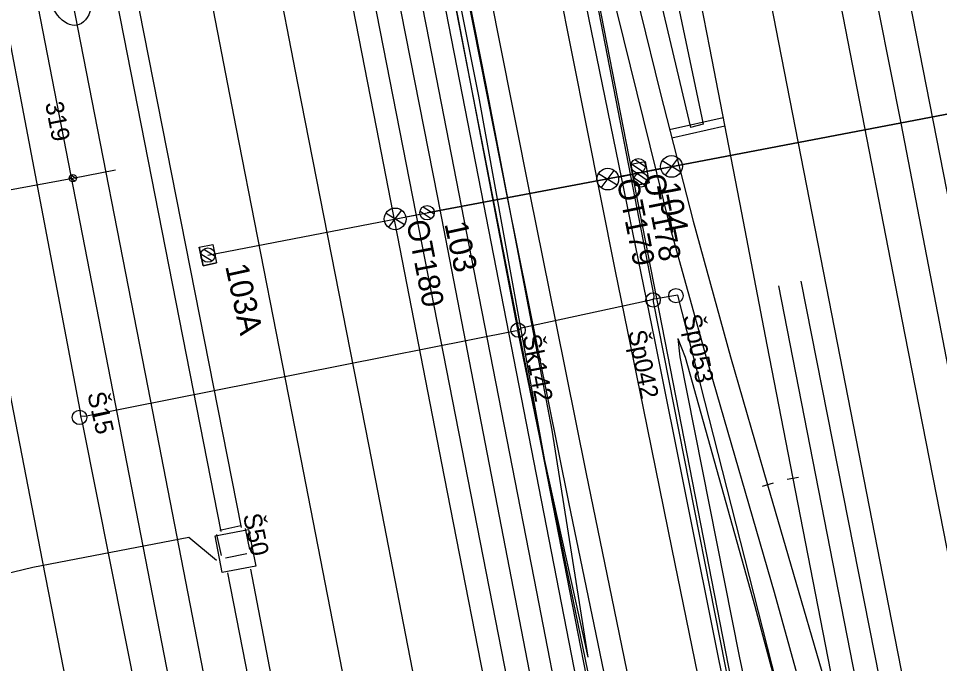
# Model space of a CAD drawing. Extents: x -545846 to -545044, y -1122650 to -1119108.
# Drawn here: x -545534.5 to -545470.6, y -1120354 to -1120309.2 of the extents above; entities that cross this region are included whole.
import ezdxf

# ---------------------------------------------------------------- set-up
doc = ezdxf.new("R2010")
doc.units = 0
for name, color, linetype in [('osvětlené plochy-hodnota-obrys', 7, 'Continuous'), ('Vrstva 1', 7, 'Continuous'), ('Vrstva 1 - Koleje', 7, 'Continuous'), ('Vrstva 11', 7, 'Continuous'), ('Vrstva 11 - Trakce', 7, 'Continuous'), ('Vrstva 12 - Trakce zaklady', 7, 'Continuous'), ('Vrstva 2 - Vyhybky', 7, 'Continuous'), ('Vrstva 25', 7, 'Continuous'), ('Vrstva 26', 7, 'Continuous'), ('Vrstva 28 - zabzar', 7, 'Continuous'), ('Vrstva 34', 7, 'Continuous'), ('Vrstva 35', 7, 'Continuous'), ('Vrstva 36', 7, 'Continuous'), ('Vrstva 4 - Teren - stezky - prechody - plochy', 7, 'Continuous'), ('Vrstva 43', 7, 'Continuous'), ('Vrstva 44', 7, 'Continuous'), ('Vrstva 49', 7, 'Continuous'), ('Vrstva 7 - Namezniky-vystroj', 7, 'Continuous')]:
    doc.layers.add(name, color=color, linetype=linetype)

msp = doc.modelspace()

# ---------------------------------------------------------------- linework, layer by layer
at = {"layer": 'osvětlené plochy-hodnota-obrys'}
for points in [[(-545607.519, -1119727.517), (-545482.536, -1120367.871), (-545465.73, -1120446.743)], [(-545611.105, -1119760.367), (-545492.389, -1120368.615), (-545475.582, -1120447.487)], [(-545605.8, -1119934.355), (-545489.142, -1120534.587)]]:
    msp.add_lwpolyline(points, dxfattribs=at)
at = {"layer": 'Vrstva 1'}
for points in [[(-545474.761, -1120297.023), (-545472.421, -1120309.053), (-545468.418, -1120329.586), (-545465.176, -1120346.189), (-545461.046, -1120367.441), (-545459.79, -1120373.88)], [(-545479.428, -1120297.932), (-545477.11, -1120309.858), (-545472.957, -1120331.165), (-545469.82, -1120347.196), (-545465.692, -1120368.38), (-545464.44, -1120374.79)], [(-545484.065, -1120298.835), (-545481.72, -1120310.868), (-545477.659, -1120331.714), (-545474.512, -1120347.852), (-545470.27, -1120369.601), (-545469.079, -1120375.698)], [(-545512.079, -1120304.29), (-545509.652, -1120316.729), (-545504.92, -1120341.014), (-545501.351, -1120359.337), (-545498.197, -1120375.55), (-545497.107, -1120381.183)], [(-545516.751, -1120305.199), (-545515.098, -1120313.673), (-545510.162, -1120338.881), (-545507.312, -1120353.561), (-545502.757, -1120376.885), (-545501.739, -1120382.09)], [(-545530.725, -1120307.92), (-545525.484, -1120334.817), (-545521.174, -1120356.99), (-545516.72, -1120379.861), (-545515.757, -1120384.834)], [(-545521.096, -1120307.884), (-545519.375, -1120316.749), (-545514.88, -1120339.783), (-545511.839, -1120355.373), (-545507.449, -1120377.832), (-545506.438, -1120383.01)], [(-545540.046, -1120309.735), (-545537.636, -1120322.066), (-545534.947, -1120335.844), (-545532.811, -1120346.828), (-545526.072, -1120381.352), (-545525.038, -1120386.65)]]:
    msp.add_lwpolyline(points, dxfattribs=at)
msp.add_ellipse((-545531.017, -1120306.509), major_axis=(0.614, -3.151), ratio=0.521067, dxfattribs=at)
at = {"layer": 'Vrstva 1 - Koleje'}
for points in [[(-545518.735, -1120170.873), (-545517.092, -1120179.279), (-545515.239, -1120188.8), (-545513.529, -1120197.566), (-545510.734, -1120211.886), (-545508.807, -1120221.766), (-545506.999, -1120231.05), (-545505.057, -1120241.005), (-545503.311, -1120249.961), (-545501.333, -1120260.123), (-545500.069, -1120266.614), (-545498.099, -1120276.734), (-545496.21, -1120286.398), (-545494.099, -1120296.551), (-545493.353, -1120299.814), (-545491.303, -1120308.782), (-545489.949, -1120314.331), (-545487.646, -1120323.268), (-545485.059, -1120332.675), (-545482.488, -1120341.567), (-545476.909, -1120360.737), (-545474.458, -1120373.309), (-545474.305, -1120374.094)], [(-545532.743, -1120173.486), (-545531.198, -1120181.414), (-545529.444, -1120190.408), (-545527.614, -1120199.79), (-545525.849, -1120208.859), (-545524.083, -1120217.878), (-545522.353, -1120226.804), (-545520.544, -1120236.067), (-545518.751, -1120245.244), (-545517.019, -1120254.134), (-545515.322, -1120262.818), (-545513.441, -1120272.491), (-545511.549, -1120282.172), (-545509.7, -1120291.668), (-545508.107, -1120299.843), (-545506.179, -1120309.724), (-545504.441, -1120318.636), (-545502.519, -1120328.489), (-545500.578, -1120338.445), (-545498.519, -1120349.006), (-545496.544, -1120359.143), (-545494.419, -1120370.064), (-545492.599, -1120379.398), (-545492.429, -1120380.268)], [(-545527.503, -1120175.582), (-545525.637, -1120185.143), (-545523.723, -1120194.953), (-545521.869, -1120204.454), (-545519.868, -1120214.706), (-545518.049, -1120224.023), (-545516.204, -1120233.485), (-545514.302, -1120243.235), (-545512.475, -1120252.605), (-545510.119, -1120264.679), (-545508.199, -1120274.552), (-545506.603, -1120282.757), (-545504.862, -1120291.702), (-545502.966, -1120301.337), (-545501.126, -1120310.611), (-545498.972, -1120321.418), (-545497.182, -1120330.346), (-545495.087, -1120340.689), (-545493.131, -1120350.244), (-545491.235, -1120359.489), (-545489.284, -1120368.922), (-545487.138, -1120379.232)], [(-545522.376, -1120177.035), (-545520.607, -1120186.115), (-545518.736, -1120195.699), (-545516.972, -1120204.753), (-545515.112, -1120214.314), (-545513.215, -1120224.036), (-545511.543, -1120232.598), (-545509.745, -1120241.825), (-545507.98, -1120250.879), (-545506.022, -1120260.921), (-545504.236, -1120270.098), (-545502.408, -1120279.461), (-545500.568, -1120288.895), (-545498.693, -1120298.415), (-545497.048, -1120306.715), (-545495.06, -1120316.74), (-545493.074, -1120326.625), (-545491.128, -1120336.251), (-545489.136, -1120346.042), (-545486.961, -1120356.657), (-545485.254, -1120364.907), (-545483.638, -1120372.702), (-545482.464, -1120378.318)], [(-545491.058, -1120287.923), (-545489.405, -1120296.386), (-545488.935, -1120298.789), (-545487.964, -1120303.745), (-545486.509, -1120311.24), (-545484.296, -1120322.688), (-545482.535, -1120331.849), (-545480.73, -1120341.135), (-545476.909, -1120360.737), (-545474.458, -1120373.309), (-545474.305, -1120374.094)]]:
    msp.add_lwpolyline(points, dxfattribs=at)
at = {"layer": 'Vrstva 11'}
for p, q in [((-545530.553, -1120320.486), (-545530.931, -1120320.23)), ((-545530.445, -1120320.332), (-545530.829, -1120320.073))]:
    msp.add_line(p, q, dxfattribs=at)
msp.add_lwpolyline([(-545554.83, -1120324.712), (-545530.687, -1120320.277), (-545527.734, -1120319.705)], dxfattribs=at)
msp.add_circle((-545530.687, -1120320.277), 0.25, dxfattribs=at)
at = {"layer": 'Vrstva 11 - Trakce'}
for p, q in [((-545491.701, -1120318.979), (-545490.962, -1120319.48)), ((-545491.933, -1120319.274), (-545491.15, -1120319.807)), ((-545491.747, -1120320.26), (-545490.965, -1120320.791)), ((-545491.516, -1120319.964), (-545490.775, -1120320.467)), ((-545506.388, -1120322.268), (-545505.619, -1120322.761)), ((-545506.596, -1120322.579), (-545505.817, -1120323.08)), ((-545521.799, -1120325.523), (-545521.02, -1120326.024)), ((-545521.591, -1120325.212), (-545520.822, -1120325.705))]:
    msp.add_line(p, q, dxfattribs=at)
msp.add_lwpolyline([(-545521.313, -1120325.623), (-545506.11, -1120322.679), (-545491.363, -1120319.905), (-545468.705, -1120315.571), (-545444.245, -1120310.64)], dxfattribs=at)
for centre in [(-545491.457, -1120319.414), (-545491.269, -1120320.396), (-545506.11, -1120322.679), (-545521.313, -1120325.623)]:
    msp.add_circle(centre, 0.5, dxfattribs=at)
at = {"layer": 'Vrstva 12 - Trakce zaklady'}
for p, q in [((-545491.972, -1120319.298), (-545490.99, -1120319.111)), ((-545491.689, -1120320.781), (-545490.707, -1120320.594)), ((-545521.928, -1120325.082), (-545520.968, -1120324.874)), ((-545521.648, -1120326.366), (-545520.724, -1120326.164))]:
    msp.add_line(p, q, dxfattribs=at)
for points in [[(-545491.689, -1120320.781), (-545491.972, -1120319.298), (-545490.99, -1120319.111), (-545490.707, -1120320.594), (-545491.689, -1120320.781)], [(-545490.99, -1120319.111), (-545490.99, -1120319.111), (-545490.707, -1120320.594), (-545490.707, -1120320.594)], [(-545491.972, -1120319.298), (-545491.972, -1120319.298), (-545491.689, -1120320.781), (-545491.689, -1120320.781)], [(-545521.928, -1120325.082), (-545520.968, -1120324.874), (-545520.724, -1120326.164), (-545521.648, -1120326.366), (-545521.928, -1120325.082)], [(-545520.968, -1120324.874), (-545520.968, -1120324.874), (-545520.724, -1120326.164), (-545520.724, -1120326.164)], [(-545521.928, -1120325.082), (-545521.928, -1120325.082), (-545521.648, -1120326.366), (-545521.648, -1120326.366)]]:
    msp.add_lwpolyline(points, dxfattribs=at)
at = {"layer": 'Vrstva 2 - Vyhybky'}
for p, q in [((-545482.104, -1120341.456), (-545482.872, -1120341.678)), ((-545480.337, -1120341.059), (-545481.123, -1120341.211))]:
    msp.add_line(p, q, dxfattribs=at)
for points in [[(-545480.73, -1120341.135), (-545476.909, -1120360.737), (-545474.458, -1120373.309), (-545474.305, -1120374.094)], [(-545482.488, -1120341.567), (-545476.909, -1120360.737)]]:
    msp.add_lwpolyline(points, dxfattribs=at)
at = {"layer": 'Vrstva 25'}
for p, q in [((-545488.513, -1120319.862), (-545489.8, -1120319.077)), ((-545488.697, -1120318.863), (-545489.603, -1120320.068)), ((-545494.029, -1120320.947), (-545493.123, -1120319.742)), ((-545489.892, -1120319.61), (-545491.363, -1120319.905)), ((-545494.213, -1120319.948), (-545492.926, -1120320.733)), ((-545492.834, -1120320.2), (-545491.363, -1120319.905)), ((-545508.961, -1120322.706), (-545507.677, -1120323.498)), ((-545508.782, -1120323.706), (-545507.869, -1120322.507)), ((-545507.582, -1120322.966), (-545506.11, -1120322.679))]:
    msp.add_line(p, q, dxfattribs=at)
msp.add_lwpolyline([(-545468.705, -1120315.571), (-545491.363, -1120319.905), (-545506.11, -1120322.679)], dxfattribs=at)
for centre in [(-545489.153, -1120319.463), (-545493.573, -1120320.347), (-545508.323, -1120323.108)]:
    msp.add_circle(centre, 0.754, dxfattribs=at)
at = {"layer": 'Vrstva 26'}
for points in [[(-545553.19, -1120335.75), (-545550.92, -1120335.78), (-545549.12, -1120343.46), (-545548.16, -1120350.83), (-545533.46, -1120347.3), (-545522.63, -1120345.2), (-545520.72, -1120346.81)], [(-545548.16, -1120350.83), (-545533.46, -1120347.3), (-545522.63, -1120345.2)]]:
    msp.add_lwpolyline(points, dxfattribs=at)
at = {"layer": 'Vrstva 28 - zabzar'}
msp.add_lwpolyline([(-545462.079, -1120374.328), (-545462.26, -1120373.53), (-545462.48, -1120372.51), (-545464.57, -1120361.29), (-545466.59, -1120351.17), (-545466.74, -1120350.25), (-545466.9, -1120349.27), (-545470.43, -1120330.98), (-545473.23, -1120316.45), (-545476.28, -1120301.06), (-545477.51, -1120293.63), (-545477.85, -1120292.58)], dxfattribs=at)
at = {"layer": 'Vrstva 34'}
for p, q in [((-545520.499, -1120344.715), (-545519.031, -1120344.407)), ((-545518.735, -1120344.601), (-545518.427, -1120346.069)), ((-545520.385, -1120346.479), (-545520.693, -1120345.011)), ((-545518.621, -1120346.365), (-545520.089, -1120346.673))]:
    msp.add_line(p, q, dxfattribs=at)
at = {"layer": 'Vrstva 35'}
for points in [[(-545520.396, -1120344.82), (-545528.092, -1120305.503)], [(-545518.988, -1120344.527), (-545526.713, -1120305.301)], [(-545512.782, -1120384.251), (-545519.924, -1120347.678)], [(-545511.33, -1120383.967), (-545518.345, -1120347.435)]]:
    msp.add_lwpolyline(points, dxfattribs=at)
at = {"layer": 'Vrstva 36'}
msp.add_line((-545520.322, -1120347.67), (-545520.322, -1120347.67), dxfattribs=at)
for points in [[(-545520.808, -1120345.124), (-545518.494, -1120344.674), (-545517.99, -1120347.211), (-545520.322, -1120347.67), (-545520.808, -1120345.124)], [(-545520.808, -1120345.124), (-545518.494, -1120344.674), (-545517.99, -1120347.211), (-545520.322, -1120347.67), (-545520.808, -1120345.124)], [(-545518.494, -1120344.674), (-545518.494, -1120344.674)], [(-545520.808, -1120345.124), (-545520.808, -1120345.124)], [(-545517.99, -1120347.211), (-545517.99, -1120347.211)]]:
    msp.add_lwpolyline(points, dxfattribs=at)
at = {"layer": 'Vrstva 4 - Teren - stezky - prechody - plochy'}
for points in [[(-545627.289, -1119622.488), (-545623.041, -1119643.798), (-545614.848, -1119686.378), (-545604.257, -1119740.381), (-545596.077, -1119782.585), (-545587.168, -1119828.353), (-545576.202, -1119884.317), (-545565.971, -1119936.976), (-545553.74, -1119999.834), (-545541.535, -1120062.236), (-545531.079, -1120116.013), (-545520.819, -1120168.515), (-545508.831, -1120230.344), (-545499.12, -1120279.845), (-545497.248, -1120289.164), (-545495.162, -1120299.078), (-545493.408, -1120306.853), (-545489.261, -1120323.659), (-545486.768, -1120332.638), (-545482.019, -1120349.033), (-545479.258, -1120359.037), (-545477.044, -1120368.814), (-545475.362, -1120376.928)], [(-545624.215, -1119622.224), (-545623.342, -1119622.007), (-545620.608, -1119632.171), (-545618.464, -1119642.593), (-545609.99, -1119685.9), (-545599.422, -1119740.168), (-545590.883, -1119784.038), (-545582.301, -1119828.162), (-545571.506, -1119883.387), (-545561.049, -1119937.185), (-545548.968, -1119999.368), (-545536.73, -1120062.107), (-545526.255, -1120115.744), (-545515.983, -1120168.544), (-545503.995, -1120229.495), (-545494.446, -1120278.921), (-545489.088, -1120306.388), (-545486.967, -1120316.535), (-545487.846, -1120316.754)], [(-545624.215, -1119622.224), (-545621.684, -1119634.807), (-545620.048, -1119643.216), (-545611.648, -1119686.181), (-545601.152, -1119739.942), (-545592.571, -1119783.992), (-545583.867, -1119828.341), (-545573.059, -1119883.823), (-545562.652, -1119937.218), (-545550.46, -1119999.458), (-545538.284, -1120062.171), (-545527.796, -1120116.054), (-545517.608, -1120168.62), (-545505.551, -1120230.109), (-545495.948, -1120279.349), (-545494.121, -1120288.848), (-545492.075, -1120298.544), (-545490.237, -1120306.578), (-545487.846, -1120316.754)], [(-545628.853, -1119622.763), (-545624.686, -1119644.063), (-545616.354, -1119686.873), (-545605.869, -1119740.58), (-545597.619, -1119782.547), (-545588.666, -1119828.365), (-545577.778, -1119884.555), (-545567.555, -1119936.921), (-545555.278, -1120000.024), (-545543.118, -1120062.357), (-545532.633, -1120116.151), (-545522.436, -1120168.075), (-545510.345, -1120230.332), (-545500.633, -1120280.001), (-545495.304, -1120307.199), (-545490.342, -1120331.504), (-545485.9, -1120353.688), (-545480.839, -1120378)], [(-545488.754, -1120379.549), (-545491.925, -1120363.788), (-545496.278, -1120342.782), (-545500.506, -1120321.731), (-545508.599, -1120280.828), (-545518.82, -1120228.621), (-545531.029, -1120165.923), (-545540.626, -1120116.248), (-545552.245, -1120057.042), (-545557.488, -1120030.03), (-545563.439, -1119999.512), (-545572.128, -1119954.79), (-545581.61, -1119906.246), (-545591.458, -1119855.639), (-545600.962, -1119806.943), (-545610.434, -1119758.233), (-545616.648, -1119726.461), (-545621.696, -1119701.088), (-545622.533, -1119696.196), (-545623.462, -1119696.331)], [(-545490.916, -1120379.972), (-545493.99, -1120364.147), (-545502.163, -1120322.09), (-545510.164, -1120281.035), (-545520.235, -1120229.023), (-545532.517, -1120166.017), (-545542.296, -1120116.028), (-545553.809, -1120057.082), (-545558.932, -1120030.597), (-545564.969, -1119999.794), (-545573.753, -1119955.036), (-545583.127, -1119906.578), (-545593.017, -1119855.856), (-545602.553, -1119806.891), (-545612.123, -1119758.671), (-545618.333, -1119726.047), (-545620.676, -1119713.873), (-545622.612, -1119701.558), (-545623.462, -1119696.331)], [(-545495.535, -1120380.876), (-545498.596, -1120365.093), (-545507.092, -1120321.572), (-545515.017, -1120281.173), (-545524.994, -1120229.535), (-545536.771, -1120169.47), (-545546.676, -1120118.787), (-545557.312, -1120064.079), (-545563.312, -1120033.308), (-545569.884, -1119999.645), (-545578.452, -1119955.82), (-545587.921, -1119907.338), (-545597.812, -1119856.591), (-545607.33, -1119807.681), (-545610.119, -1119793.19), (-545611.535, -1119784.447), (-545612.6, -1119777.287), (-545613.018, -1119774.47), (-545612.047, -1119774.376)], [(-545493.924, -1120380.561), (-545496.951, -1120365.161), (-545505.376, -1120321.611), (-545513.278, -1120281.443), (-545523.478, -1120229.493), (-545535.102, -1120169.56), (-545545.054, -1120118.579), (-545554.55, -1120069.937), (-545561.701, -1120033.181), (-545568.213, -1119999.317), (-545576.806, -1119955.508), (-545586.262, -1119907.136), (-545605.677, -1119807.326), (-545612.047, -1119774.376)], [(-545480.19, -1120327.425), (-545474.356, -1120356.955), (-545470.624, -1120376)], [(-545481.74, -1120327.759), (-545475.994, -1120357.133), (-545472.25, -1120376.318)], [(-545488.716, -1120331.415), (-545488.2, -1120332.717), (-545483.361, -1120350.001), (-545480.647, -1120360.215), (-545478.471, -1120369.339), (-545476.879, -1120377.224)], [(-545488.716, -1120331.415), (-545488.577, -1120332.696), (-545484.459, -1120353.475), (-545479.322, -1120377.703)]]:
    msp.add_lwpolyline(points, dxfattribs=at)
at = {"layer": 'Vrstva 43'}
for centre in [(-545488.844, -1120328.44), (-545490.428, -1120328.733), (-545499.796, -1120330.829), (-545530.225, -1120336.889)]:
    msp.add_circle(centre, 0.5, dxfattribs=at)
at = {"layer": 'Vrstva 44'}
for points in [[(-545629.268, -1120065.402), (-545629.634, -1120087.876), (-545630.039, -1120112.736), (-545629.044, -1120137.319), (-545628.839, -1120137.845), (-545628.579, -1120138.408), (-545605.178, -1120154.045), (-545604.485, -1120154.235), (-545603.868, -1120154.242), (-545567.82, -1120146.847), (-545567.035, -1120147.195), (-545566.786, -1120147.869), (-545557.769, -1120194.412), (-545548.548, -1120241.228), (-545548.384, -1120241.623), (-545548.361, -1120241.936), (-545539.222, -1120288.885), (-545539.174, -1120289.236), (-545530.2, -1120336.386), (-545530.153, -1120336.813), (-545530.009, -1120337.37), (-545520.393, -1120385.741)], [(-545508.45, -1120235.904), (-545498.915, -1120284.406), (-545490.386, -1120328.463), (-545490.4, -1120328.688)], [(-545518.036, -1120237.5), (-545508.365, -1120286.112), (-545499.871, -1120330.664), (-545499.82, -1120330.883)], [(-545488.706, -1120328.407), (-545490.227, -1120328.66), (-545490.4, -1120328.688), (-545490.707, -1120328.776), (-545499.59, -1120330.699), (-545499.82, -1120330.883), (-545500.022, -1120330.904)], [(-545480.443, -1120377.922), (-545483.628, -1120363.18), (-545490.393, -1120328.833), (-545490.4, -1120328.688)], [(-545477.006, -1120377.249), (-545480.026, -1120362.567), (-545488.706, -1120328.407)], [(-545500.021, -1120330.903), (-545529.867, -1120336.834), (-545530.153, -1120336.813)], [(-545489.516, -1120379.698), (-545492.775, -1120365.061), (-545499.794, -1120330.975), (-545499.82, -1120330.883)]]:
    msp.add_lwpolyline(points, dxfattribs=at)
at = {"layer": 'Vrstva 49'}
for points in [[(-545521.468, -1120219.739), (-545516.167, -1120245.05), (-545511.487, -1120269.708), (-545506.698, -1120293.734), (-545502.546, -1120314.587), (-545497.953, -1120339.881), (-545494.957, -1120353.535)], [(-545521.468, -1120219.739), (-545515.677, -1120244.752), (-545510.858, -1120269.666), (-545506.045, -1120293.556), (-545502.041, -1120313.823), (-545497.445, -1120337.782), (-545494.957, -1120353.535)]]:
    msp.add_lwpolyline(points, dxfattribs=at)
at = {"layer": 'Vrstva 7 - Namezniky-vystroj'}
for p, q in [((-545489.289, -1120316.893), (-545485.578, -1120316.057)), ((-545489.139, -1120317.474), (-545485.464, -1120316.646))]:
    msp.add_line(p, q, dxfattribs=at)

# ---------------------------------------------------------------- texts
at = {"layer": 'Vrstva 11'}
msp.add_text('319', height=1.25, rotation=281.02822, dxfattribs=at).set_placement((-545532.619, -1120315.081))
at = {"layer": 'Vrstva 11 - Trakce'}
for s, rotation, p in [('104', 280.80383, (-545490.193, -1120320.7)), ('103', 282.30182, (-545504.92, -1120323.443)), ('103A', 282.30182, (-545520.123, -1120326.387))]:
    msp.add_text(s, height=1.6, rotation=rotation, dxfattribs=at).set_placement(p)
at = {"layer": 'Vrstva 25'}
for s, rotation, p in [('OT179', 281.36008, (-545492.953, -1120320.466)), ('OT178', 281.36008, (-545491.138, -1120320.13)), ('OT180', 281.03793, (-545507.551, -1120323.315))]:
    msp.add_text(s, height=1.5, rotation=rotation, dxfattribs=at).set_placement(p)
at = {"layer": 'Vrstva 34'}
msp.add_text('Š50', height=1.25, rotation=281.83177, dxfattribs=at).set_placement((-545518.89, -1120343.688))
at = {"layer": 'Vrstva 43'}
for s, rotation, p in [('Šp053', 280.99979, (-545488.355, -1120329.845)), ('Šk142', 280.99979, (-545499.491, -1120331.242)), ('Šp042', 280.99979, (-545492.17, -1120330.941)), ('Š15', 282.98932, (-545529.693, -1120335.257))]:
    msp.add_text(s, height=1.25, rotation=rotation, dxfattribs=at).set_placement(p)

doc.saveas('drawing.dxf')
